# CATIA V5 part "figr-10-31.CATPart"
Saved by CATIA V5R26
Part number: Part1
Bounding box of the stored display mesh (mm): x -84 to 53, y -93.367 to 104.555, z -56.529 to 41.172
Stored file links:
  D:\_Deepak\CATIA\CATIA V5 2015 Parts Files\Part files\Partfiles\c10_catia_v5_6r2015_prt\figr-10-31-1.CATPart
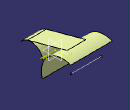
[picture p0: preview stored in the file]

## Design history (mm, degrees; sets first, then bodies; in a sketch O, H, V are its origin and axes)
Body1 (main body)
  Sketch1 on yz-plane, origin (0, 0, 0), H (0, 1, 0), V (0, 0, 1)
    arc A1 centre (-59.8904, -36.5447) radius 41.17 from (-93.3668, -12.5802) to (-23.896, -56.5291) cw
  Extrude1: Lim1 20, Lim2 42, Element1 Sketch1
  Sketch2 on yz-plane, origin (0, 0, 0), H (0, 1, 0), V (0, 0, 1)
    arc A1 centre (78.3128, -29.0048) radius 70.3421 from (104.5554, 36.2588) to (11.1367, -49.8706) ccw
  Extrude2: Lim1 53, Lim2 84, Element1 Sketch2
  Sketch3 on xy-plane, origin (0, 0, 0), H (1, 0, 0), V (0, 1, 0)
    line L1 (-58.0902, 93.9265) -> (40.4277, 93.9265)
    horizontal: L1 H
  Sweep1: type Segment, Spine Sketch3, Length1 20, Length2 0, GuideSurf (Extrude1; Extrude2)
